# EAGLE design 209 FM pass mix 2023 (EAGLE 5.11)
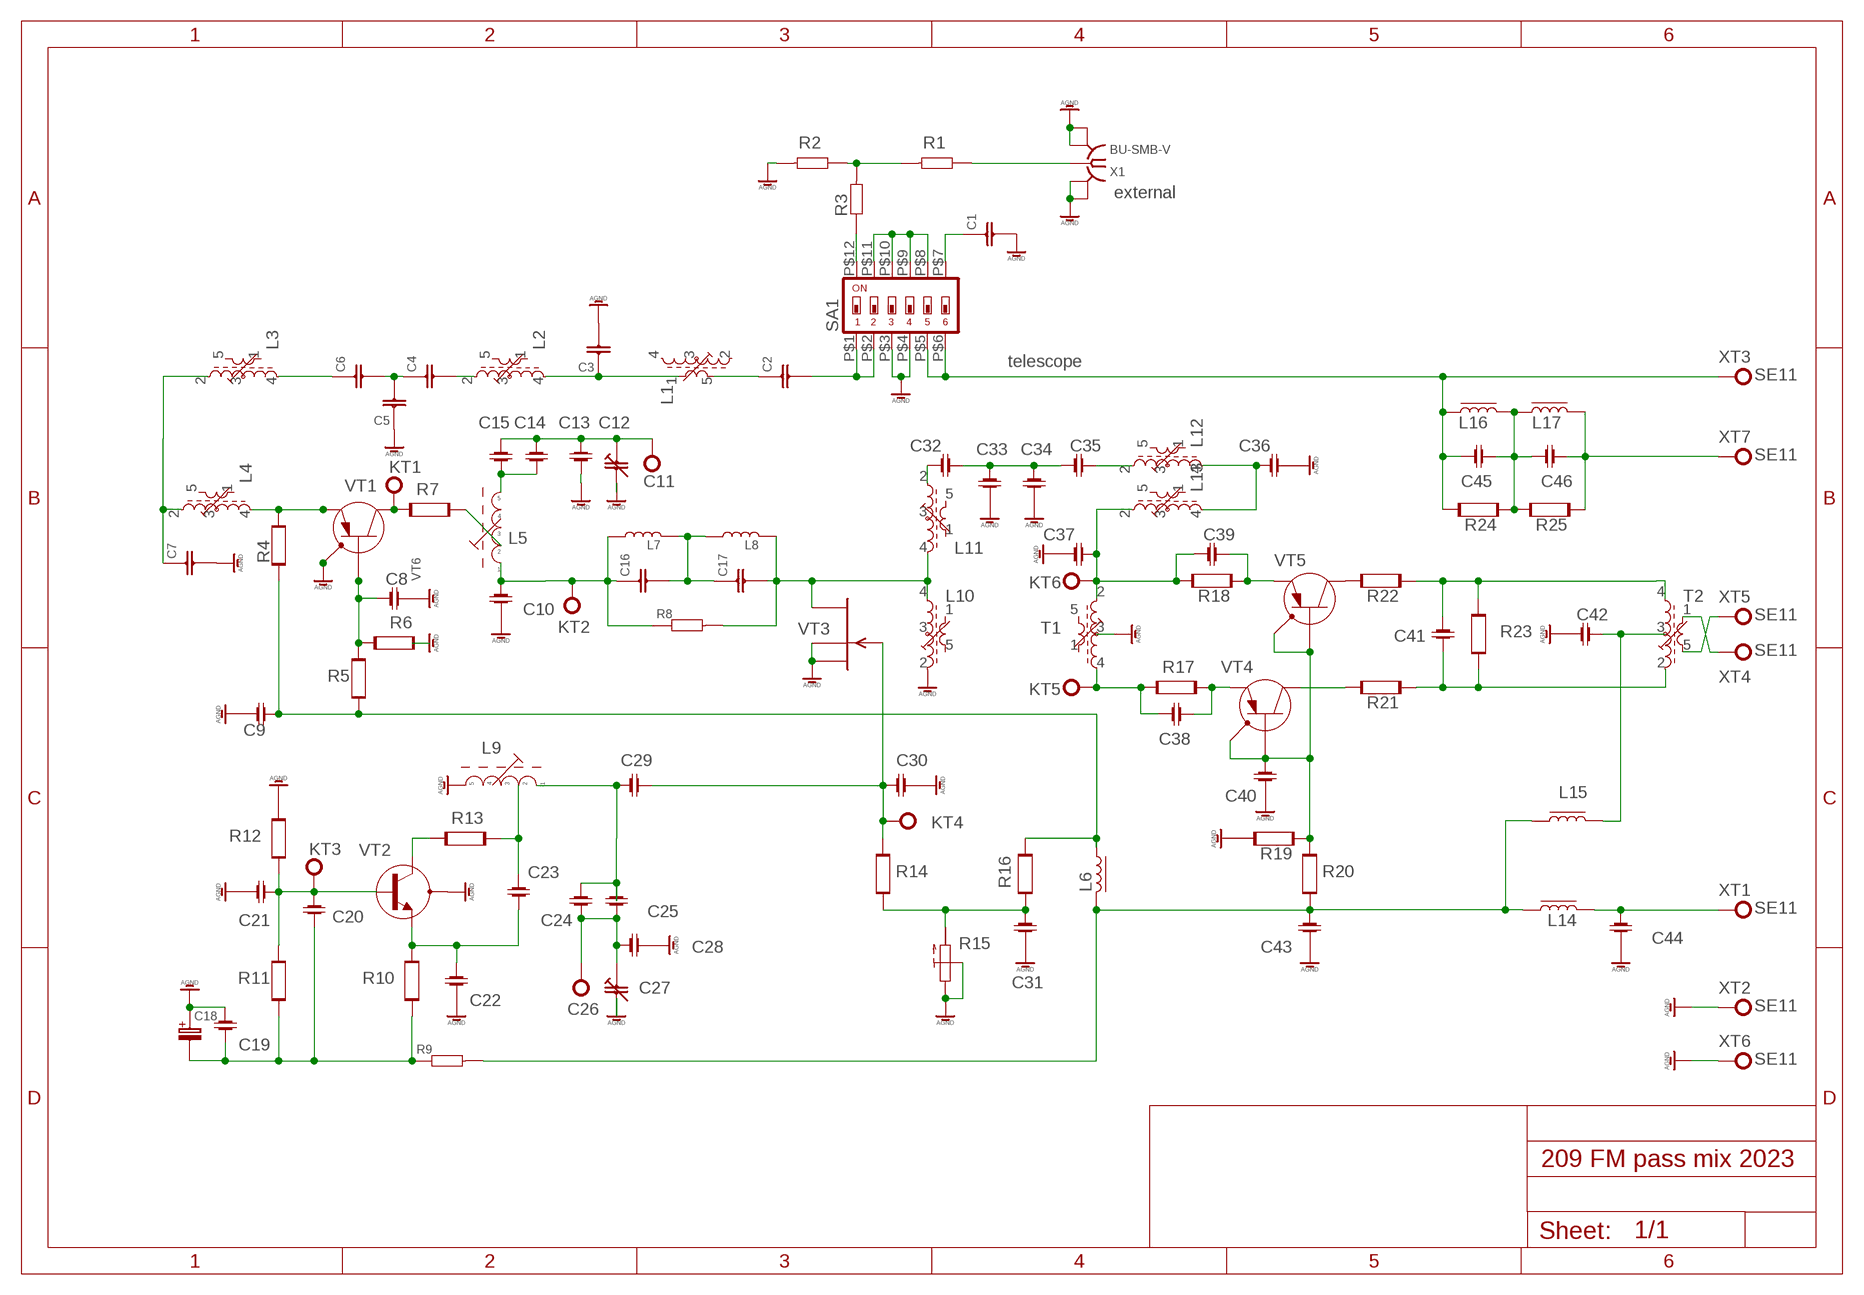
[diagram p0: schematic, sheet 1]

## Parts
C1  C-EUC0805  [C0805]
C2  C-EUC0805  [C0805]
C3  C-EUC0805  [C0805]
C4  C-EUC0805  [C0805]
C5  C-EUC0805  [C0805]
C6  C-EUC0805  [C0805]
C7  C-EUC0805  [C0805]
C8  C-1206-0805  [RC-SMD-UNIV]
C9  C-1206-0805  [RC-SMD-UNIV]
C10  C-1206-0805  [RC-SMD-UNIV]
C11  SE11  [SE11]
C12  C-TRIMMTZ03  [CTRIMTZ03]
C13  C-1206-0805  [RC-SMD-UNIV]
C14  C-1206-0805  [RC-SMD-UNIV]
C15  C-1206-0805  [RC-SMD-UNIV]
C16  C-EUC0805  [C0805]
C17  C-EUC0805  [C0805]
C18  CPOL-EUE3.5-8  [E3,5-8]
C19  C-1206-0805  [RC-SMD-UNIV]
C20  C-1206-0805  [RC-SMD-UNIV]
C21  C-1206-0805  [RC-SMD-UNIV]
C22  C-1206-0805  [RC-SMD-UNIV]
C23  C-1206-0805  [RC-SMD-UNIV]
C24  C-1206-0805  [RC-SMD-UNIV]
C25  C-1206-0805  [RC-SMD-UNIV]
C26  SE11  [SE11]
C27  C-TRIMMTZ03  [CTRIMTZ03]
C28  C-1206-0805  [RC-SMD-UNIV]
C29  C-1206-0805  [RC-SMD-UNIV]
C30  C-1206-0805  [RC-SMD-UNIV]
C31  C-1206-0805  [RC-SMD-UNIV]
C32  C-1206-0805  [RC-SMD-UNIV]
C33  C-1206-0805  [RC-SMD-UNIV]
C34  C-1206-0805  [RC-SMD-UNIV]
C35  C-1206-0805  [RC-SMD-UNIV]
C36  C-1206-0805  [RC-SMD-UNIV]
C37  C-1206-0805  [RC-SMD-UNIV]
C38  C-1206-0805  [RC-SMD-UNIV]
C39  C-1206-0805  [RC-SMD-UNIV]
C40  C-1206-0805  [RC-SMD-UNIV]
C41  C-1206-0805  [RC-SMD-UNIV]
C42  C-1206-0805  [RC-SMD-UNIV]
C43  C-1206-0805  [RC-SMD-UNIV]
C44  C-1206-0805  [RC-SMD-UNIV]
C45  C-1206-0805  [RC-SMD-UNIV]
C46  C-1206-0805  [RC-SMD-UNIV]
KT1  SE11  [SE11]
KT2  SE11  [SE11]
KT3  SE11  [SE11]
KT4  SE11  [SE11]
KT5  SE11  [SE11]
KT6  SE11  [SE11]
L1  71-5-24513  [71-5]
L2  71-5-24513  [71-5]
L3  71-5-24513  [71-5]
L4  71-5-24513  [71-5]
L5  L-UKW-RFSEL  [L-UKW]
L6  L-US0207/10  [0207/10]
L7  L-US-AIRL0603  [L0603]
L8  L-US-AIRL0603  [L0603]
L9  L-UKW-OSC  [L-UKW]
L10  71-5-24513  [71-5]
L11  71-5-24513  [71-5]
L12  71-5-24513  [71-5]
L13  71-5-24513  [71-5]
L14  L-US0207/10  [0207/10]
L15  L-US0207/10  [0207/10]
L16  L-US0207/2V  [0207/2V]
L17  L-US0207/2V  [0207/2V]
R1  R-EU_R0805W  [R0805W]
R2  R-EU_R0805W  [R0805W]
R3  R-EU_R0805W  [R0805W]
R4  R-1206-0805  [RC-SMD-UNIV]
R5  R-1206-0805  [RC-SMD-UNIV]
R6  R-1206-0805  [RC-SMD-UNIV]
R7  R-1206-0805  [RC-SMD-UNIV]
R8  R-EU_R0805  [R0805]
R9  R-EU_0207/10  [0207/10]
R10  R-1206-0805  [RC-SMD-UNIV]
R11  R-1206-0805  [RC-SMD-UNIV]
R12  R-1206-0805  [RC-SMD-UNIV]
R13  R-1206-0805  [RC-SMD-UNIV]
R14  R-1206-0805  [RC-SMD-UNIV]
R15  R-TRIMM  [CA6-V]
R16  R-1206-0805  [RC-SMD-UNIV]
R17  R-1206-0805  [RC-SMD-UNIV]
R18  R-1206-0805  [RC-SMD-UNIV]
R19  R-1206-0805  [RC-SMD-UNIV]
R20  R-1206-0805  [RC-SMD-UNIV]
R21  R-1206-0805  [RC-SMD-UNIV]
R22  R-1206-0805  [RC-SMD-UNIV]
R23  R-1206-0805  [RC-SMD-UNIV]
R24  R-1206-0805  [RC-SMD-UNIV]
R25  R-1206-0805  [RC-SMD-UNIV]
SA1  SWS006-127  [SMS-006-127]
T1  71-5-24513  [71-5]
T2  71-5-24513  [71-5]
VT1  VT-GT322  [VT-TO-18-4]
VT2  RUS-GT311  [RUS-GT311]
VT3  AP324  [SMALL-CROSS]
VT4  VT-GT322  [VT-TO-18-4]
VT5  VT-GT322  [VT-TO-18-4]
VT6  VT-GT330-KT3123  [CROSS-7MM]
X1  BU-SMB-V  [BU-SMB-V]
XT1  SE11  [SE11]
XT2  SE11  [SE11]
XT3  SE11  [SE11]
XT4  SE11  [SE11]
XT5  SE11  [SE11]
XT6  SE11  [SE11]
XT7  SE11  [SE11]

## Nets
AGND: C1.2 C3.2 C5.1 C7.2 C8.P$2 C9.P$1 C10.P$1 C12.2(A) C13.P$2 C18.+ C19.P$2 C21.P$1 C22.P$1 C27.2(A) C28.P$2 C30.P$2 C31.P$1 C33.P$1 C34.P$1 C36.P$2 C37.P$1 C40.P$1 C42.P$1 C43.P$1 C44.P$1 L9.P$1 L10.2(A1) R2.2 R6.P$1 R12.P$2 R15.E R15.S R19.P$2 SA1.P$3 SA1.P$4 T1.3(Z) VT1.4(SH) VT2.S VT3.P$2(S1) VT3.P$4(S2) VT6.P$4(SH) X1.2(GND) X1.3 X1.4 X1.5 XT2.MP XT6.MP
N$1: C18.- C19.P$1 C20.P$1 R9.1 R10.P$1 R11.P$1
N$2: C37.P$2 C39.P$1 KT6.MP L13.2(A1) R18.P$2 T1.2(A1)
N$3: C41.P$1 R21.P$1 R23.P$1 T2.2(A1)
N$4: C6.1 L3.4(E1)
N$5: C29.P$2 C30.P$1 KT4.MP R14.P$2 VT3.P$1(G)
N$6: C42.P$2 L15.2 T2.3(Z)
N$7: C31.P$2 R14.P$1 R15.A R16.P$2
N$8: C7.1 L3.2(A1) L4.2(A1)
N$9: C2.2 SA1.P$1 SA1.P$2
N$10: L4.4(E1) R4.P$2 VT1.1(E) VT6.P$1(E)
N$11: R3.1 SA1.P$12
N$12: C43.P$2 L6.2 L14.1 L15.1 R9.2 R20.P$1
N$13: C8.P$1 R5.P$2 R6.P$2 VT1.2(B) VT6.P$2(B)
N$14: C11.MP C12.1(E) C13.P$1 C14.P$2 C15.P$2
N$15: KT1.MP R7.P$2 VT1.3(C) VT6.P$3(C)
N$16: L5.P$2 R7.P$1
N$17: C14.P$1 C15.P$1 L5.P$4
N$18: C38.P$1 KT5.MP R17.P$2 T1.4(E1)
N$19: C17.2 L8.2 L10.4(E1) L11.4(E1) R8.2 VT3.P$3(D)
N$20: C32.P$1 L11.2(A1)
N$21: C32.P$2 C33.P$2 C34.P$2 C35.P$1
N$22: C35.P$2 L12.2(A1)
N$23: C24.P$1 C25.P$1 C26.MP C27.1(E) C28.P$1
N$24: C41.P$2 R22.P$1 R23.P$2 T2.4(E1)
N$25: C44.P$2 L14.2 XT1.MP
N$26: C2.1 L1.5(A2)
N$27: T2.5(A2) XT5.MP
N$28: R22.P$2 VT5.3(C)
N$29: C9.P$2 L6.1 R4.P$1 R5.P$1 R16.P$1
N$30: C20.P$2 C21.P$2 KT3.MP R11.P$2 R12.P$1 VT2.B
N$31: C22.P$2 C23.P$1 R10.P$2 VT2.E
N$32: R13.P$2 VT2.C
N$33: C23.P$2 L9.P$4 R13.P$1
N$34: C24.P$2 C25.P$2 C29.P$1 L9.P$2
N$35: C38.P$2 R17.P$1 VT4.1(E)
N$36: C39.P$2 R18.P$1 VT5.1(E)
N$37: C40.P$2 R19.P$1 R20.P$2 VT4.2(B) VT4.4(SH) VT5.2(B) VT5.4(SH)
N$38: C3.1 L1.1(E2) L2.4(E1)
N$39: R21.P$2 VT4.3(C)
N$40: C45.P$2 C46.P$1 L16.2 L17.2 R24.P$1 R25.P$2
N$41: C1.1 SA1.P$7
N$42: SA1.P$8 SA1.P$9 SA1.P$10 SA1.P$11
N$43: R1.2 R2.1 R3.2
N$44: R1.1 X1.1
N$45: C45.P$1 L16.1 R24.P$2 SA1.P$5 SA1.P$6 XT3.MP
N$46: C4.2 L2.2(A1)
N$47: C46.P$2 L17.1 R25.P$1 XT7.MP
N$48: C4.1 C5.2 C6.2
N$49: T2.1(E2) XT4.MP
N$50: C10.P$2 C16.1 KT2.MP L5.P$3 L7.1 R8.1
N$51: C36.P$1 L12.4(E1) L13.4(E1)
N$53: C16.2 C17.1 L7.2 L8.1
Unconnected: L1.2(A1) L1.3(Z) L1.4(E1) L1.S1 L1.S2 L2.1(E2) L2.3(Z) L2.5(A2) L2.S1 L2.S2 L3.1(E2) L3.3(Z) L3.5(A2) L3.S1 L3.S2 L4.1(E2) L4.3(Z) L4.5(A2) L4.S1 L4.S2 L10.1(E2) L10.3(Z) L10.5(A2) L10.S1 L10.S2 L11.1(E2) L11.3(Z) L11.5(A2) L11.S1 L11.S2 L12.1(E2) L12.3(Z) L12.5(A2) L12.S1 L12.S2 L13.1(E2) L13.3(Z) L13.5(A2) L13.S1 L13.S2 T1.1(E2) T1.5(A2) T1.S1 T1.S2 T2.S1 T2.S2

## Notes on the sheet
- external
- telescope

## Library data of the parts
C1-C7 C16 C17 = rcl:C-EU: CAPACITOR, European symbol
C8-C10 C13-C15 C19-C25 C28-C46 = OKEAH:C-1206-0805
C11 C26 KT1-KT6 XT1-XT7 = solpad:SE11: SOLDER PAD
C12 C27 = rcl:C-TRIMM: Trimm capacitor
C18 = rcl:CPOL-EU: POLARIZED CAPACITOR, European symbol
L1-L4 L10-L13 T1 T2 = inductor-neosid:71-5-: TRANSFORMER adjustable filter transformer with tap; OC_FARNELL: unknown; OC_NEWARK: unknown
L5 = OKEAH:L-UKW-RFSEL
L6 L14-L17 = rcl:L-US: INDUCTOR, American symbol
L7 L8 = rcl:L-US-AIR
L9 = OKEAH:L-UKW-OSC
R1-R3 R8 R9 = rcl:R-EU_: RESISTOR, European symbol
R4-R7 R10-R14 R16-R25 = OKEAH:R-1206-0805
R15 = rcl:R-TRIMM: Trimm resistor
SA1 = smd-special:SWS006-127
VT1 VT4 VT5 = OKEAH:VT-GT322
VT2 = transistor-npn:RUS-GT311
VT3 = transistor-fet:AP324
VT6 = OKEAH:VT-GT330-KT3123
X1 = xcon-coax:BU-SMB-V: FEMALE SMB CONNECTOR Radiall distributor RS 112-2993; OC_FARNELL: unknown; OC_NEWARK: unknown

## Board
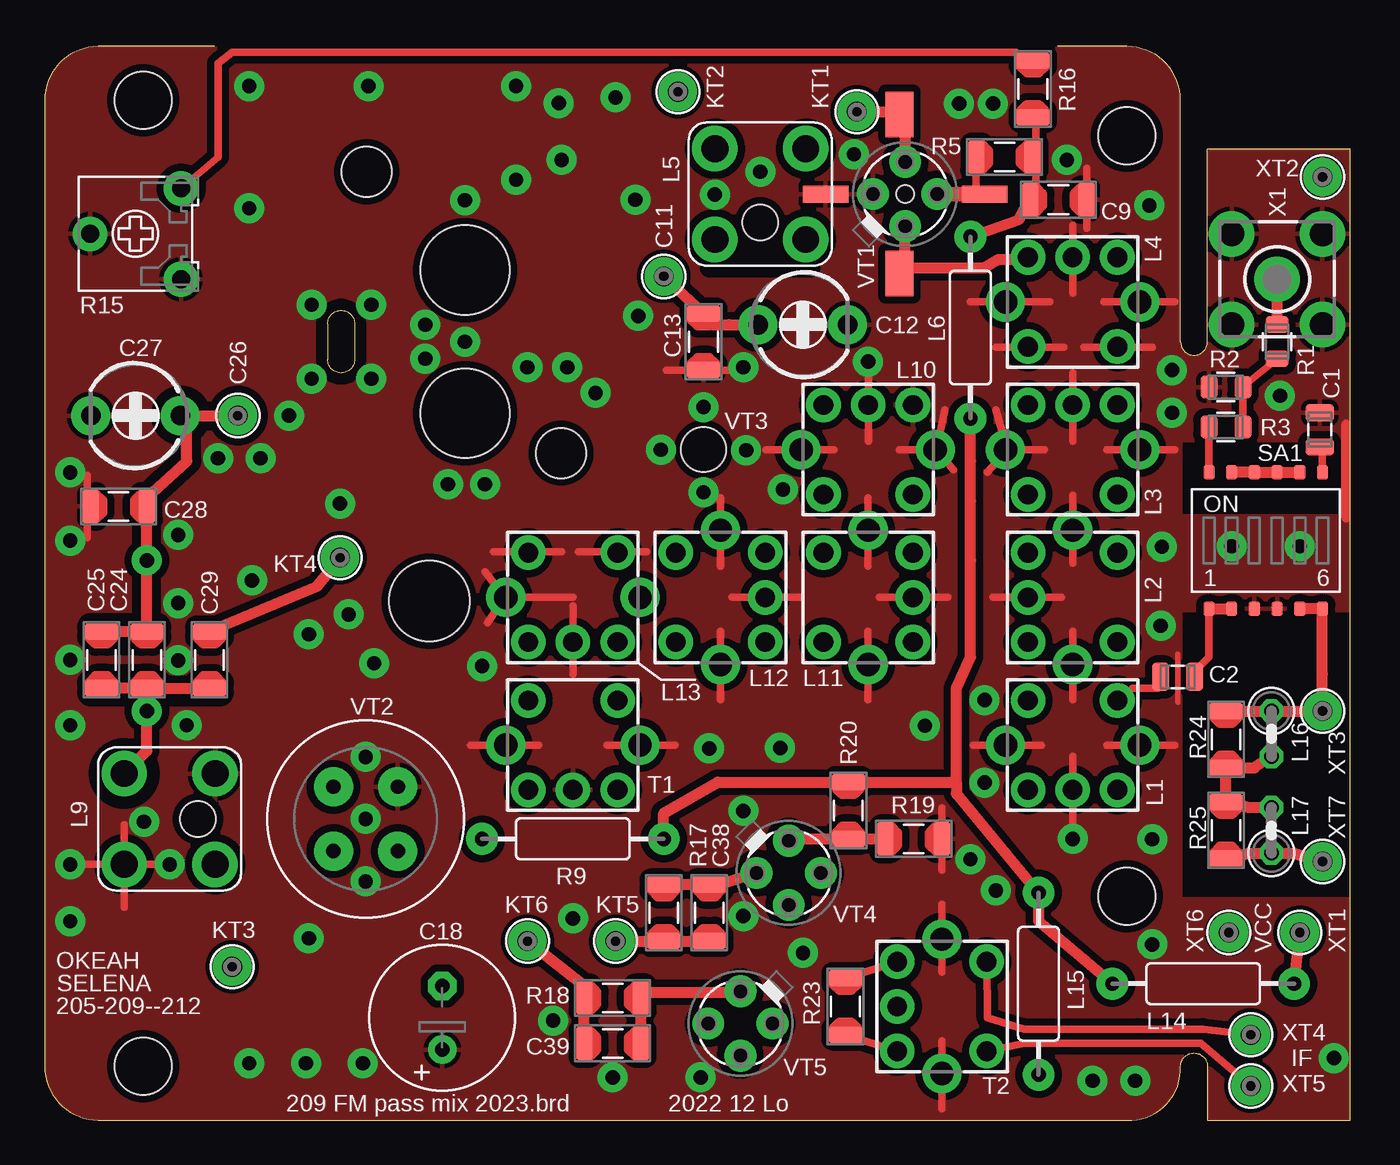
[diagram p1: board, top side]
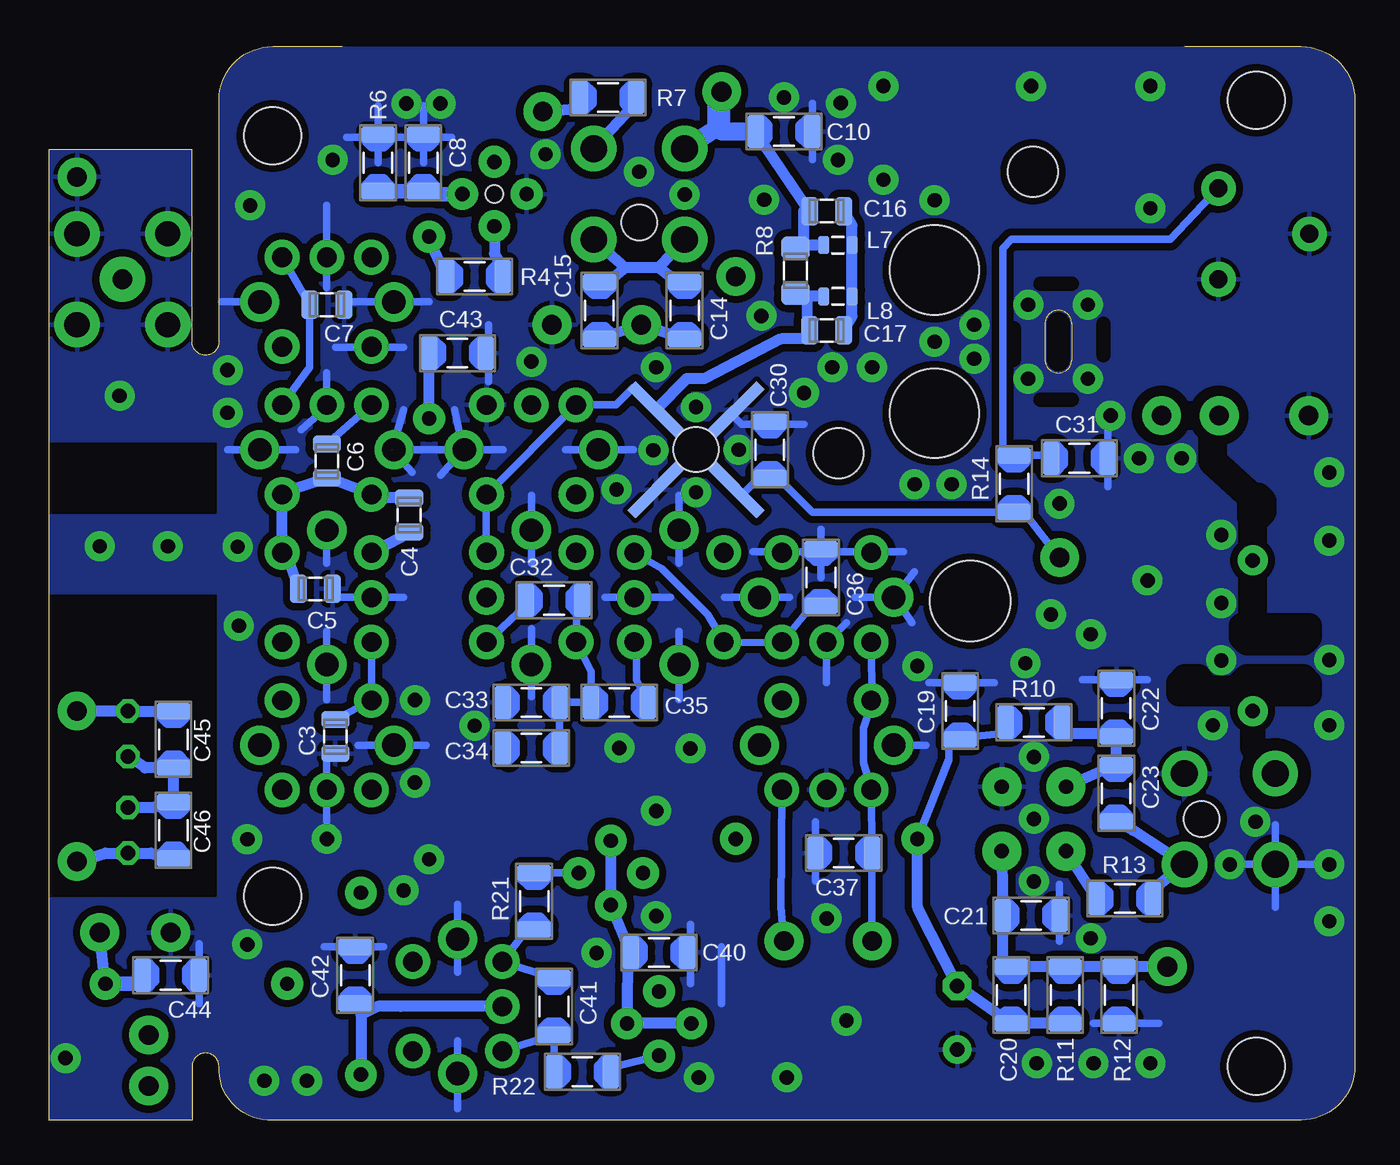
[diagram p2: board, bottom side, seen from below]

Size 73 x 60 mm. Coordinates in mm from the lower left corner, seen from the top.
Outline: 56.62,60 60.5,60 arc-90 63.5,57 63.5,43.5 arc180 65,43.5 65,54.25 73,54.25 73,0 65,0 65,3 arc180 63.5,3 arc-96 60.5,0 3,0 arc-90 0,3 0,57 arc-90 3,60 9.5,60
Copper layers (1*16): Top 0.035mm / dielectric 1.5mm / Bottom 0.035mm
Design rules "default *": minimum track width 10mil, minimum drill 24mil, track to track 8mil, track to pad 8mil, pad to pad 8mil, via to via 8mil, smd to smd 8mil, copper to edge 0mil, drill to drill 8mil, minimum pad ring 10mil, minimum via ring 8mil, stop-mask expansion 4mil, vias tented up to drill 0mil, thermal gap 10mil
Holes 3.2 mm at 5.5,57 60.5,55 5.5,3 60.5,12.5
Holes 4.5 mm at 21.5,29
Holes 5 mm at 23.5,39.5 23.5,47.5
Holes 2.8 mm at 18,53 28.86,37.27
tRestrict: area 3.2,18.1 to 5.7,20.6; area 9.8,38.4 to 11.7,40.3; area 6.7,38.4 to 8.6,40.3; 18 lines
bRestrict: area 3.2,18.1 to 5.7,20.6; area 9.8,38.4 to 11.7,40.3; area 6.7,38.4 to 8.6,40.3; 44 lines
Milling: 4 lines

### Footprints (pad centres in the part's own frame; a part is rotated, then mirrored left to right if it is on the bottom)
C0805 = smd 0.952 x 1.587: 1 -0.953,0; 2 0.953,0
RC-SMD-UNIV = smd 0.965 x 1.93: P$1 -1.587,0; P$2 1.587,0
SE11 = drill 1.1 pad 2.159 round: MP 0,0
CTRIMTZ03 = drill 1.1 pad 2.184 round: 1 0,2.5; 2 0,-2.5
E3,5-8 = drill 0.813 pad 1.6 round: + -1.778,0 | drill 0.813 pad 1.6 octagon: - 1.778,0
71-5 = drill 1.1 pad 1.93 round: 1 2.5,-2.5; 2 2.5,2.5; 3 0,2.5; 4 -2.5,2.5; 5 -2.5,-2.5 | drill 1.3 pad 2.184 round: S1 -3.75,0; S2 3.75,0
L-UKW = drill 1.5 pad 2.54 round: P$1 2.54,-2.54; P$2 2.54,2.54; P$3 -2.54,2.54; P$4 -2.54,-2.54 | hole 2: 0,-1.587
0207/10 = drill 0.8 pad 1.778 round: 1 -5.08,0; 2 5.08,0
L0603 = smd 0.635 x 1.016: 1 -0.794,0; 2 0.794,0
0207/2V = drill 0.813 octagon: 1 -1.27,0; 2 1.27,0
R0805W = smd 0.952 x 1.27: 1 -0.953,0 | smd 0.925 x 1.27: 2 0.953,0
R0805 = smd 1.27 x 1.587: 1 -1.27,0; 2 1.27,0
CA6-V = drill 1 pad 1.93 round: A 2.54,-2.54; E -2.54,-2.54; S 0,2.54
SMS-006-127 = smd 0.635 x 0.813: P$1 0,-3.81; P$2 1.27,-3.81; P$3 2.54,-3.81; P$4 3.81,-3.81; P$5 5.08,-3.81; P$6 6.35,-3.81; P$7 6.35,3.81; P$8 5.08,3.81; P$9 3.81,3.81; P$10 2.54,3.81; P$11 1.27,3.81; P$12 0,3.81
VT-TO-18-4 = drill 0.8 pad 1.778 round: 1 1.27,-1.27; 2 1.27,1.27; 3 -1.27,1.27; 4 -1.27,-1.27
RUS-GT311 = drill 0.8 pad 2.184 round: B 0,2.54; C 2.54,0; E 0,-2.54; S -2.54,0
SMALL-CROSS = smd 0.635 x 3.86: P$1 0,-3.175; P$3 0,3.175 | smd 3.86 x 0.635: P$2 3.175,0; P$4 -3.175,0 | hole 2.5: 0,0
CROSS-7MM = smd 2.54 x 0.952: P$1 4.445,-0.635; P$3 -4.445,-0.635; P$5 4.445,0; P$6 -4.445,0 | smd 0.952 x 2.54: P$2 0,4.445; P$4 0,-4.445 | hole 1: 0,0
BU-SMB-V = drill 1.1 pad 2.54 round: 1 0,0 | drill 1.4 pad 2.54 round: 2 -2.54,2.54; 3 2.54,2.54; 4 2.54,-2.54; 5 -2.54,-2.54

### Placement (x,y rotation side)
C1  71.28,38.58 90 top
C2  63.34,24.77 0 top
C3  56.99,21.43 270 bottom
C4  52.86,33.81 270 bottom
C5  58.1,29.69 180 bottom
C6  57.47,36.83 270 bottom
C7  57.47,45.56 0 bottom
C8  52.07,53.5 90 bottom
C9  56.67,51.44 180 top
C10  31.91,55.25 180 bottom
C11  34.61,47.15 0 top
C12  42.39,44.45 90 top
C13  36.83,43.5 270 top
C14  37.47,45.24 270 bottom
C15  42.23,45.24 270 bottom
C16  29.53,50.8 0 bottom
C17  29.53,44.13 180 bottom
C18  22.22,5.72 90 top
C19  22.07,22.86 90 bottom
C20  19.21,6.99 90 bottom
C21  18.1,11.43 180 bottom
C22  13.33,23.02 270 bottom
C23  13.34,18.26 270 bottom
C24  5.71,25.72 270 top
C25  3.17,25.72 270 top
C26  10.79,39.37 0 top
C27  5.08,39.37 270 top
C28  4.13,34.29 180 top
C29  9.21,25.72 90 top
C30  32.7,37.47 90 bottom
C31  15.4,36.99 180 bottom
C32  44.77,29.05 0 bottom
C33  46.04,23.34 0 bottom
C34  46.04,20.8 0 bottom
C35  41.12,23.34 0 bottom
C36  29.84,30.32 90 bottom
C37  28.58,14.92 0 bottom
C38  37.15,11.59 90 top
C39  31.75,4.29 0 top
C40  38.89,9.37 180 bottom
C41  44.77,6.35 270 bottom
C42  55.88,8.1 270 bottom
C43  50.16,42.86 180 bottom
C44  66.2,8.1 180 bottom
C45  66.04,21.27 270 bottom
C46  66.04,16.19 270 bottom
KT1  45.4,56.36 0 top
KT2  35.4,57.47 0 top
KT3  10.48,8.57 0 top
KT4  16.51,31.43 0 top
KT5  31.91,10 0 top
KT6  26.99,10 90 top
L1  57.47,20.96 180 top
L2  57.47,29.21 90 top
L3  57.47,37.47 0 top
L4  57.47,45.72 0 top
L5  40.01,51.75 0 top
L6  51.75,44.29 270 top
L7  28.89,48.89 0 bottom
L8  28.89,46.04 180 bottom
L9  6.99,16.83 90 top
L10  46.04,37.46 0 top
L11  46.04,29.21 270 top
L12  37.78,29.21 270 top
L13  29.53,29.21 180 top
L14  64.77,7.62 0 top
L15  55.56,7.62 270 top
L16  68.58,21.59 270 top
L17  68.58,16.19 90 top
R1  68.9,43.5 270 top
R2  66.04,40.96 180 top
R3  66.04,38.73 0 top
R4  49.21,47.15 0 bottom
R5  53.66,53.82 180 top
R6  54.61,53.5 270 bottom
R7  41.75,57.15 180 bottom
R8  31.27,47.47 270 bottom
R9  29.53,15.72 0 top
R10  17.94,22.23 0 bottom
R11  16.19,6.99 90 bottom
R12  13.18,6.99 270 bottom
R13  12.86,12.38 180 bottom
R14  19.05,35.56 270 bottom
R15  5.08,49.53 90 top
R16  55.25,57.63 90 top
R17  34.61,11.59 270 top
R18  31.75,6.83 180 top
R19  48.58,15.72 0 top
R20  44.93,17.3 270 top
R21  45.88,12.22 90 bottom
R22  43.18,2.7 0 bottom
R23  44.77,6.35 270 top
R24  66.04,21.27 90 top
R25  66.04,16.19 90 top
SA1  65.09,32.39 0 top
T1  29.53,20.96 180 top
T2  50.16,6.35 90 top
VT1  48.1,51.75 315 top
VT2  17.94,16.83 225 top
VT3  36.83,37.47 45 bottom
VT4  41.59,13.81 225 top
VT5  38.89,5.4 135 top
VT6  48.1,51.75 270 top
X1  68.9,46.99 0 top
XT1  70.17,10.48 90 top
XT2  71.44,52.71 45 top
XT3  71.44,22.86 180 top
XT4  67.42,4.76 0 top
XT5  67.42,1.91 0 top
XT6  66.2,10.48 0 top
XT7  71.44,14.45 90 top

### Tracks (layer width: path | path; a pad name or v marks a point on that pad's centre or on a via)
AGND  (via drill 0.8 pad 1.68)  (1 unrouted)
  Top 0.305: 63.34,23.34 63.34,26.04
  Top 0.406: 58.26,49.85 58.26,53.18 | 2.22,14.29 6.83,14.29 | 25.72,29.21 24.61,30.64 | 50.16,0.64 50.16,4.45 | 72.71,33.66 72.71,38.89 | 34.77,41.91 38.58,41.91 | 4.45,11.91 4.45,16.51 | 50.16,13.97 50.16,17.46 | 2.38,32.54 2.38,36.04 | 31.43,20.96 35.24,20.96 | 23.81,20.96 27.62,20.96 | 29.53,24.92 29.53,28.73 | 25.72,29.21 29.53,29.21 | 24.77,27.78 25.72,29.21 | 37.78,30.96 37.78,34.77 | 37.78,23.5 37.78,27.31 | 46.04,30.96 46.04,34.77 | 46.04,23.5 46.04,27.31 | 46.67,29.21 50.48,29.21 | 38.42,29.21 42.23,29.21 | 40.32,37.47 44.13,37.47 | 47.78,37.47 49.85,37.47 | 49.85,37.47 50.32,39.69 | 49.85,37.47 50.8,36.35 | 51.75,45.72 56.2,45.72 | 59.21,45.72 63.18,45.72 | 53.18,43.18 56.99,43.18 | 58.1,43.18 61.91,43.18 | 57.47,46.2 57.47,50.01 | 59.37,37.47 63.18,37.47 | 57.47,37.94 57.47,41.75 | 53.82,37.47 55.88,37.47 | 52.7,36.2 53.82,37.47 | 53.18,39.69 53.82,37.47 | 57.47,31.12 57.47,34.93 | 57.47,23.5 57.47,27.31 | 53.02,29.21 56.83,29.21 | 51.91,20.96 55.72,20.96 | 59.37,20.96 63.18,20.96 | 57.47,16.51 57.47,20.32 | 50.16,8.26 50.16,12.07 | 46.04,37.94 46.04,41.75 | 29.84,31.75 33.66,31.75 | 25.08,31.75 28.89,31.75
  Top 0.5: 72.74,33.66 72.74,38.89
  Bottom 0.406: 30.32,53.66 30.32,56.83 | 13.81,35.4 13.81,38.58 | 35.4,6.51 35.4,9.68 | 50.16,8.26 50.16,12.07 | 50.16,0.64 50.16,4.45 | 54.29,9.68 57.63,9.68 | 64.61,6.51 64.61,9.84 | 48.42,41.28 48.42,44.45 | 30.8,38.89 34.29,38.89 34.77,39.37 34.92,39.37 | 2.22,14.29 6.83,14.29 | 4.45,11.91 4.45,16.51 | 57.47,16.67 57.47,20.48 | 57.47,31.12 57.47,33.02 | 51.91,20.96 55.72,20.96 | 57.47,23.5 57.47,27.31 | 53.18,29.21 56.99,29.21 | 47.62,37.47 49.85,37.47 | 49.85,37.47 53.82,37.47 | 53.82,37.47 | 53.82,37.47 54.13,37.47 | 57.47,39.85 57.47,41.75 | 59.21,37.47 63.02,37.47 | 53.18,43.18 56.99,43.18 | 51.75,45.72 56.36,45.72 | 63.34,45.72 61.12,45.72 | 57.47,46.51 57.47,51.12 | 40.32,37.47 44.13,37.47 | 46.04,31.12 46.04,34.93 | 46.04,23.65 46.04,27.46 | 37.78,31.12 37.78,34.93 | 37.78,23.5 37.78,27.31 | 38.26,29.21 41.91,29.21 | 31.59,29.21 35.24,29.21 | 29.84,30.32 29.84,33.02 | 27.94,29.21 25.72,29.21 24.77,27.78 | 25.72,29.21 24.61,30.64 | 10.95,5.4 14.61,5.4 | 23.97,20.96 25.88,20.96 | 30,31.75 33.66,31.75 | 25.24,31.75 28.89,31.75 | 49.85,37.47 50.32,39.69 | 53.82,37.47 53.18,39.69 | 53.82,37.47 52.7,36.2 | 49.85,37.47 51.12,36.04 | 50.48,54.93 56.36,54.93 | 52.07,53.5 52.07,56.67 | 54.61,53.5 54.61,56.67 | 20.16,24.45 23.81,24.45 | 11.59,24.61 15.24,24.61 | 16.51,10 16.51,13.18 | 57.47,39.85 58.9,38.58 | 37.15,7.62 37.15,10.95 | 30.16,13.34 30.16,16.67 | 29.53,24.45 29.53,26.67 | 29.53,26.67 28.42,27.78
  other vias: 58.58,2.2 57.47,15.72 36.83,35.08 62.39,27.62 39.05,11.4 62.45,32.04 70.17,32.07 33.18,44.94 63.02,39.53 24.45,25.37 66.36,32.07 22.54,35.53 37.47,51.73 40.01,53 18.41,25.53 7.46,25.69 37.15,20.77 14.61,3.17 36.67,2.38 17.78,3.18 17.94,13.34 1.43,11.11 14.76,10.16 31.75,2.38 6.99,14.29 16.99,28.26 18.26,41.43 14.92,41.43 14.92,45.56 18.26,45.56 21.27,44.45 11.43,57.79 41.28,35.24 31.91,57.15 34.45,37.47 28.73,56.83 36.83,39.85 23.5,43.5 39.21,37.44 17.94,20.29 23.5,51.41 11.43,3.18 41.12,20.8 29.53,11.27 61.91,15.69 61.91,9.81 72.07,3.47 60.96,2.2 53.18,12.83 53.02,56.81 63.02,41.91 11.43,50.96 39.05,42.07 28.89,53.66 61.75,51.12 45.24,53.98 69.06,40.48 33.02,51.44 26.35,52.55 30.8,40.64 49.21,22.04 52.55,23.47 52.55,18.86 42.39,9.34 39.05,17.28 28.42,5.56 17.94,16.83 13.65,39.37 12.06,36.99 21.27,42.55 24.61,35.53 26.99,42.07 29.21,42.07 14.76,27.15 7.46,28.89 11.59,30.16 16.51,34.45 9.68,36.99 7.46,32.7 1.43,36.2 1.43,32.39 7.94,22.07 1.43,22.07 1.43,25.72 5.56,16.67 18.1,57.79 26.35,57.79 1.43,14.29 51.75,14.58 46.04,42.39 51.12,56.81 57.15,53.66
  pour Top (isolate 0.406): 0.12,3 arc90 3,0.13 60.75,0.13 arc90 63.38,3 arc-90 64.25,3.88 arc-90 65.12,3 65.12,0.13 72.88,0.13 72.87,12.35 63.5,12.35 63.5,28.5 72.88,28.5 72.88,33.75 63.5,33.75 63.5,38 72.88,38 72.88,54.13 65.12,54.13 65.12,43.5 arc-90 64.25,42.63 arc-90 63.38,43.5 63.38,57 arc90 60.5,59.88 3.12,59.88 arc90 0.12,57
  pour Bottom (isolate 0.406): 3,0.13 60.62,0.13 arc90 63.38,2.88 63.38,3 arc-90 64.25,3.88 arc-90 65.12,3 65.12,0.13 72.88,0.13 72.88,12.35 63.5,12.35 63.5,29.5 72.88,29.5 72.88,33.75 63.5,33.75 63.5,38 72.88,38 72.88,54.13 65.12,54.13 65.12,43.5 arc-90 64.25,42.63 arc-90 63.38,43.5 63.38,57 arc90 60.5,59.88 3,59.88 arc90 0.12,57 0.12,3 arc90
N$1
  Bottom 0.406: R10.P$1 19.84,21.59 21.43,21.43 C19.P$1 22.7,21.11 22.7,20.16 R9.1
  Bottom 0.61: R9.1 24.45,11.91 C18.- 19.68,5.72 C20.P$1 R11.P$1
N$2
  Top 0.61: C39.P$1 R18.P$2 30,7.62 KT6.MP
  Bottom 0.406: KT6.MP C37.P$2 T1.2 27.46,20 27.46,21.91 26.99,23.34 L13.2
N$3
  Top 0.406: R23.P$1 T2.2
  Bottom 0.406: R23.P$1 T2.2 46.51,10.32 R21.P$1
N$4
  Bottom 0.406: L3.4 C6.1
N$5
  Top 0.61: C29.P$2 15.24,29.85 KT4.MP
  Bottom 0.406: VT3.P$1 34.29,34.93 33.34,35.88 C30.P$1 31.91,35.56 30.32,33.97 R14.P$2 18.73,33.97 arc90 18.41,33.66 18.26,33.66 KT4.MP | VT3.P$1
N$6
  Bottom 0.406: 55.56,5.87 C42.P$2
  Bottom 0.61: T2.3 53.34,6.35 54.61,6.35 55.56,5.87 L15.2
N$7
  Top 0.406: R15.A 9.68,53.82 9.68,56.52 9.68,59.06 10.48,59.69 15.24,59.69 53.18,59.69 54.29,59.69 R16.P$2
  Bottom 0.406: C31.P$2 16.99,37.15 R14.P$1 19.37,37.15 19.68,37.47 19.68,38.58 19.68,48.74 19.21,49.21 10.32,49.21 R15.A
N$8
  Bottom 0.406: L4.2 C7.1 58.42,42.07 L3.2
N$9
  Top 0.406: SA1.P$1 65.09,25.88 64.45,25.24 C2.2
  Top 0.61: SA1.P$1 SA1.P$2 SA1.P$1
N$10
  Top 0.61: VT6.P$1 47.62,47.31 47.78,47.15 48.1,47.63 | 48.1,47.63 VT1.1 | L4.4 54.29,48.1 53.34,48.1 52.55,47.63 48.1,47.63
  Bottom 0.61: VT1.1 48.1,48.42 47.62,47.63 R4.P$2
N$11
  Top 0.406: SA1.P$12 65.09,37.62 R3.1
N$12
  Top 0.61: 50.96,18.26 | 50.96,18.89 50.96,18.26 | 50.96,18.89 50.96,24.13 51.75,25.88 51.75,31.27 51.75,34.61 51.75,36.83 51.75,38.58 L6.2 | 50.96,18.26 | 50.96,18.26 L15.1 55.56,11.11 L14.1 | 50.96,18.89 R20.P$1 37.62,18.89 34.61,17.15 R9.2
  Bottom 0.61: L6.2 C43.P$2
N$13
  Top 0.406: VT6.P$2 52.07,51.75 R5.P$2
  Top 0.813: VT1.2 VT6.P$2
  Bottom 0.813: VT1.2 51.28,51.75 C8.P$1 R6.P$2
N$14
  Top 0.61: C11.MP C13.P$1 37.31,44.45 38.26,44.45 C12.1
  Bottom 0.61: C14.P$2 C12.1 C15.P$2
N$15
  Top 0.61: VT1.3 48.1,56.2 VT6.P$3 47.47,56.36 KT1.MP
  Bottom 0.61: KT1.MP 43.66,56.52 R7.P$2
N$16
  Bottom 0.61: L5.P$2 40.48,56.52 R7.P$1
N$17
  Bottom 0.61: 38.89,47.63 L5.P$4 | 38.89,47.63 40.8,47.63 | C15.P$1 41.59,46.99 40.8,47.63 | 38.89,47.63 38.1,46.99 C14.P$1 | 40.8,47.63 42.23,48.9
N$18
  Top 0.61: C38.P$1 R17.P$2 KT5.MP
  Bottom 0.406: KT5.MP 32.07,11.91 T1.4
N$19
  Bottom 0.406: VT3.P$3 40.32,40.96 | 40.32,40.96 | 40.32,40.96 41.31,39.97 L10.4 | L11.4 48.58,31.75 48.58,34.93 L10.4 | L10.4
  Bottom 0.61: L8.2 30.96,46.04 R8.2 30.64,45.88 30.64,44.45 C17.2 30.64,43.66 32.07,43.66 36.35,41.43 37.35,41.43 39.05,39.69 39.05,39.71 VT3.P$3
N$20
  Bottom 0.406: L11.2 46.35,28.73 C32.P$1 | C32.P$1 46.35,29.21 C32.P$1
N$21
  Bottom 0.406: C32.P$2 43.34,29.21 43.34,28.58 43.5,28.58 43.5,26.67 42.7,25.08 C35.P$1 C33.P$2 C34.P$2
N$22
  Bottom 0.406: C35.P$2 40.16,24.61 40.16,26.04 L12.2
N$23
  Top 0.61: C26.MP C27.1 7.94,38.89 7.94,36.83 5.71,34.77 C28.P$1 C24.P$1 C25.P$1
N$24
  Top 0.406: R23.P$2 T2.4
  Bottom 0.406: T2.4 R23.P$2 R22.P$1
N$25
  Top 0.61: L14.2 XT1.MP
  Bottom 0.61: L14.2 XT1.MP
  Bottom 0.813: C44.P$2 67.79,7.62 L14.2
N$26
  Top 0.406: C2.1 62.23,24.13 60.8,24.13 L1.5
N$27
  Top 0.406: XT5.MP 64.64,4.29 62.87,4.29 61.28,4.29 54.77,4.29 T2.5
N$28
  Bottom 0.406: VT5.3 41.27,3.02 R22.P$2
N$29
  Top 0.406: C9.P$2 55.4,52.07 55.4,53.18 R5.P$1 55.4,54.13 55.4,55.56 R16.P$1
  Top 0.61: L6.1 54.45,50.32 C9.P$2
  Bottom 0.61: R4.P$1 | R4.P$1 51.75,49.21 L6.1
N$30
  Bottom 0.61: KT3.MP R12.P$1 R11.P$2 C20.P$2 19.68,8.89 C21.P$2 19.68,13.34 VT2.B
N$31
  Bottom 0.61: VT2.E C23.P$1 C22.P$2 13.81,21.59 16.19,21.59 R10.P$2
N$32
  Bottom 0.61: R13.P$2 VT2.C
N$33
  Bottom 0.61: R13.P$1 11.11,13.02 L9.P$4 9.68,14.45 12.38,16.19 C23.P$2
N$34  (via drill 0.8 pad 1.68)
  Top 0.61: L9.P$2 5.71,20.64 v5.71,22.86 C24.P$2 | C24.P$2 C25.P$2 | C24.P$2 C29.P$1
N$35
  Top 0.61: VT4.1 37.78,13.18 C38.P$2 R17.P$1
N$36
  Top 0.61: VT5.1 38.42,7.14 33.34,7.14 R18.P$1 C39.P$2
N$37
  Top 0.61: VT4.4 42.23,15.72 R20.P$2 R19.P$1
  Bottom 0.61: VT5.2 VT5.4 40.64,8.41 C40.P$2 VT4.2 VT4.4
N$38
  Bottom 0.406: C3.1 L1.1 L2.4
N$39
  Bottom 0.406: VT4.3 R21.P$2
N$40
  Top 0.61: L16.2 67.63,19.69 C45.P$2 C46.P$1 67.31,17.46 L17.2
  Bottom 0.61: L16.2 67.63,19.69 C45.P$2 C46.P$1 67.31,17.46 L17.2
N$41
  Top 0.406: C1.1 71.44,37.31 71.44,37.15 SA1.P$7
N$42
  Top 0.61: SA1.P$11 SA1.P$10 SA1.P$9 SA1.P$8
N$43
  Top 0.406: R1.2 67.15,41.12 R2.1 R3.2
N$44
  Top 0.61: R1.1 | R1.1 X1.1 | R1.1 | R1.1
N$45
  Top 0.61: SA1.P$5 SA1.P$6 71.44,24.92 XT3.MP L16.1 R24.P$2
  Bottom 0.61: R24.P$2 L16.1 XT3.MP
N$46
  Bottom 0.61: L2.2 53.34,32.54 C4.2
N$47
  Top 0.61: R25.P$1 67.31,14.92 L17.1 69.85,14.92 XT7.MP
  Bottom 0.61: 68.9,14.92 69.85,14.92 XT7.MP | R25.P$1 67.31,14.92 L17.1
N$48
  Bottom 0.406: 60.01,35.24 60.01,35.08 59.37,35.24
  Bottom 0.61: 60.01,35.08 60.01,32.39 C5.2 | C4.1 54.93,34.77 55.72,35.24 56.99,35.72 57.31,35.72 C6.2 | C6.2 59.37,35.24 | C6.2
N$49
  Top 0.406: T2.1 52.7,5.72 54.77,5.08 61.12,5.08 62.87,5.08 64.77,5.08 XT4.MP
N$50
  Bottom 0.61: C10.P$2 C16.1 30.8,50.8 30.8,49.21 R8.1 30.96,48.9 L7.1
  Bottom 1.016: C10.P$2 35.4,55.25 | 35.4,55.25 | 35.4,55.25 KT2.MP 35.72,57.47 35.72,55.4 L5.P$3
N$51
  Bottom 0.406: L12.4 38.73,30.8 36.2,28.26 35.24,26.67 L13.4 30.64,28.42 30.16,28.73 C36.P$1
N$53
  Bottom 0.61: C16.2 28.1,50.01 L7.2 L8.1 28.1,44.93 C17.1
N$55  (via drill 0.8 pad 1.68)
  other vias: 5.71,31.27

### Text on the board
tPlace: VCC | OKEAH | SELENA | 205-209--212 | IF | 209 FM pass mix 2023.brd | 2022 12 Lo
